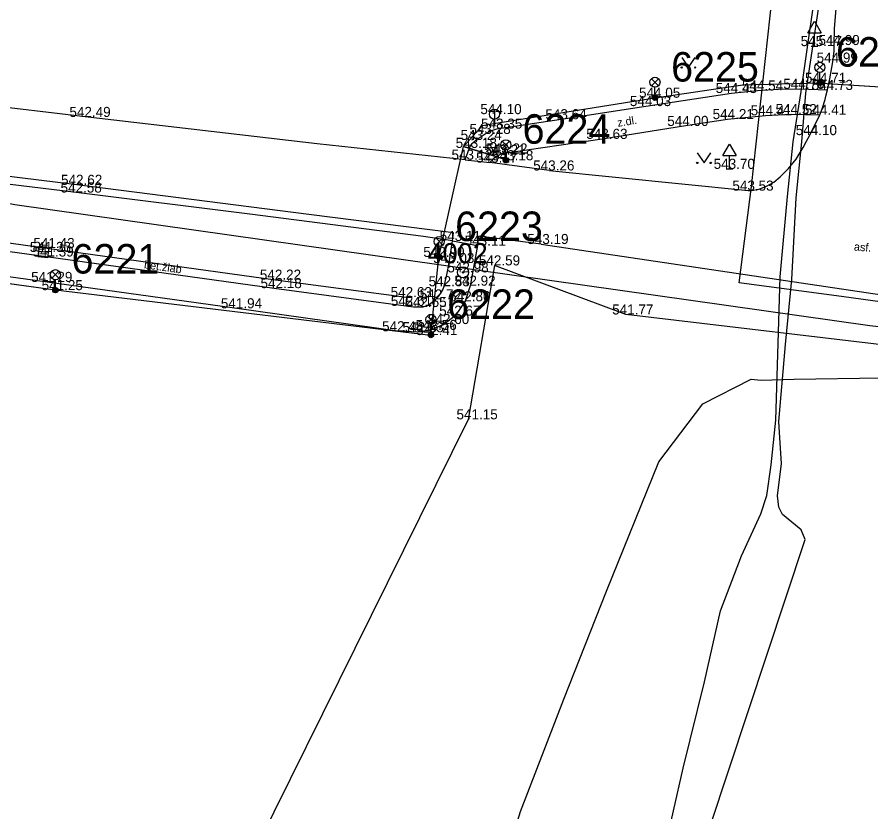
# Model space of a CAD drawing. Extents: x -669393 to -668650, y -1126925 to -1126294.
# Drawn here: x -669358 to -669294.5, y -1126585.2 to -1126526.1 of the extents above; entities that cross this region are included whole.
import ezdxf

# ---------------------------------------------------------------- set-up
doc = ezdxf.new("R2010")
doc.units = 0
for name, color, linetype in [('G_Bod_tecka', 7, 'Continuous'), ('G_Bod_vyska', 7, 'Continuous'), ('G_Bodove_pole', 7, 'Continuous'), ('G_Breh_Teren', 7, 'Continuous'), ('G_Cesty_Schody', 7, 'Continuous'), ('G_Objekty_dopravni', 7, 'Continuous'), ('G_Objekty_technicke', 7, 'Continuous'), ('G_Plochy_zpevnene', 7, 'Continuous'), ('G_Popisy_povrchu', 7, 'Continuous'), ('G_Site-kanalizace', 7, 'Continuous'), ('G_Z_ELsilove_nadz_kotovane', 7, 'Continuous'), ('G_Z_ELsilove_podz_kotovane', 7, 'Continuous'), ('G_Z_SPOJE_podz_geodeticky', 7, 'Continuous'), ('G_Z_SPOJE_podz_kotovane', 7, 'Continuous'), ('G_Z_SPOJE_podz_priblizne', 7, 'Continuous'), ('G_Zelen-okraj', 7, 'Continuous'), ('G_Zelen-Znacky', 7, 'Continuous'), ('Vrstva 1', 7, 'Continuous'), ('Vrstva 4', 7, 'Continuous'), ('Vrstva 62', 7, 'Continuous')]:
    doc.layers.add(name, color=color, linetype=linetype)

msp = doc.modelspace()

# ---------------------------------------------------------------- linework, layer by layer
at = {"layer": 'G_Bod_tecka'}
for p, q in [((-669298.71, -1126528.29), (-669298.71, -1126528.29)), ((-669297.24, -1126528.21), (-669297.24, -1126528.21)), ((-669297.38, -1126529.52), (-669297.38, -1126529.52)), ((-669302.94, -1126531.59), (-669302.94, -1126531.59)), ((-669299.84, -1126531.47), (-669299.84, -1126531.47)), ((-669298.31, -1126531.02), (-669298.31, -1126531.02)), ((-669297.75, -1126531.55), (-669297.75, -1126531.55)), ((-669310.57, -1126532.13), (-669310.57, -1126532.13)), ((-669304.89, -1126531.78), (-669304.89, -1126531.78)), ((-669311.25, -1126532.75), (-669311.25, -1126532.75)), ((-669322.51, -1126533.35), (-669322.51, -1126533.35)), ((-669302.35, -1126533.44), (-669302.35, -1126533.44)), ((-669300.44, -1126533.35), (-669300.44, -1126533.35)), ((-669298.31, -1126533.4), (-669298.31, -1126533.4)), ((-669352.95, -1126533.56), (-669352.95, -1126533.56)), ((-669317.54, -1126533.73), (-669317.54, -1126533.73)), ((-669305.18, -1126533.72), (-669305.18, -1126533.72)), ((-669322.34, -1126534.43), (-669322.34, -1126534.43)), ((-669308.45, -1126534.23), (-669308.45, -1126534.23)), ((-669323.86, -1126535.27), (-669323.86, -1126535.27)), ((-669323.2, -1126534.82), (-669323.2, -1126534.82)), ((-669314.5, -1126535.19), (-669314.5, -1126535.19)), ((-669299.06, -1126534.91), (-669299.06, -1126534.91)), ((-669324.37, -1126535.86), (-669324.37, -1126535.86)), ((-669322.16, -1126536.37), (-669322.16, -1126536.37)), ((-669321.95, -1126536.28), (-669321.95, -1126536.28)), ((-669324.68, -1126536.74), (-669324.68, -1126536.74)), ((-669322.85, -1126536.95), (-669322.85, -1126536.95)), ((-669321.66, -1126536.78), (-669321.66, -1126536.78)), ((-669318.45, -1126537.54), (-669318.45, -1126537.54)), ((-669305.02, -1126537.42), (-669305.02, -1126537.42)), ((-669353.61, -1126539.18), (-669353.61, -1126539.18)), ((-669353.56, -1126538.61), (-669353.56, -1126538.61)), ((-669303.65, -1126539.04), (-669303.65, -1126539.04)), ((-669325.62, -1126542.78), (-669325.62, -1126542.78)), ((-669319.04, -1126543.01), (-669319.04, -1126543.01)), ((-669356.04, -1126543.6), (-669356.04, -1126543.6)), ((-669355.77, -1126543.31), (-669355.77, -1126543.31)), ((-669323.76, -1126543.13), (-669323.76, -1126543.13)), ((-669355.84, -1126543.94), (-669355.84, -1126543.94)), ((-669326.61, -1126543.97), (-669326.61, -1126543.97)), ((-669325.88, -1126544.42), (-669325.88, -1126544.42)), ((-669322.5, -1126544.6), (-669322.5, -1126544.6)), ((-669324.84, -1126545.12), (-669324.84, -1126545.12)), ((-669355.94, -1126545.83), (-669355.94, -1126545.83)), ((-669338.79, -1126545.66), (-669338.79, -1126545.66)), ((-669326.24, -1126546.15), (-669326.24, -1126546.15)), ((-669324.32, -1126546.11), (-669324.32, -1126546.11)), ((-669355.16, -1126546.44), (-669355.16, -1126546.44)), ((-669338.88, -1126546.29), (-669338.88, -1126546.29)), ((-669329.05, -1126546.96), (-669329.05, -1126546.96)), ((-669326.9, -1126547.13), (-669326.9, -1126547.13)), ((-669324.68, -1126547.27), (-669324.68, -1126547.27)), ((-669341.83, -1126547.79), (-669341.83, -1126547.79)), ((-669329.1, -1126547.61), (-669329.1, -1126547.61)), ((-669327.95, -1126547.69), (-669327.95, -1126547.69)), ((-669325.44, -1126548.34), (-669325.44, -1126548.34)), ((-669312.73, -1126548.25), (-669312.73, -1126548.25)), ((-669327.2, -1126549.4), (-669327.2, -1126549.4)), ((-669326.25, -1126548.96), (-669326.25, -1126548.96)), ((-669329.7, -1126549.5), (-669329.7, -1126549.5)), ((-669328.18, -1126549.57), (-669328.18, -1126549.57)), ((-669327.23, -1126549.78), (-669327.23, -1126549.78)), ((-669324.45, -1126556.05), (-669324.45, -1126556.05))]:
    msp.add_line(p, q, dxfattribs=at)
at = {"layer": 'G_Bodove_pole'}
for radius in [0.412, 0.05]:
    msp.add_circle((-669324.84, -1126545.12), radius, dxfattribs=at)
at = {"layer": 'G_Breh_Teren'}
for points in [[(-669325.62, -1126542.78), (-669327.79, -1126542.44), (-669340.7, -1126540.78), (-669353.61, -1126539.18), (-669369.57, -1126537.24), (-669385.54, -1126535.32), (-669388.78, -1126534.926)], [(-669325.62, -1126542.78), (-669327.79, -1126542.44), (-669340.7, -1126540.78), (-669353.61, -1126539.18), (-669369.57, -1126537.24), (-669385.54, -1126535.32), (-669388.78, -1126534.926)], [(-669253.52, -1126555.73), (-669254.03, -1126555.64), (-669254.54, -1126555.56), (-669256.55, -1126555.24), (-669258.55, -1126554.92), (-669262.47, -1126554.31), (-669266.4, -1126553.72), (-669269.9, -1126553.23), (-669273.41, -1126552.75), (-669278.15, -1126552.15), (-669282.9, -1126551.62), (-669286.72, -1126551.24), (-669290.54, -1126550.87), (-669312.73, -1126548.25), (-669322.5, -1126544.6)]]:
    msp.add_lwpolyline(points, dxfattribs=at)
at = {"layer": 'G_Cesty_Schody'}
msp.add_lwpolyline([(-669385.563, -1126539.824), (-669383.61, -1126540.11), (-669368.3, -1126542.23), (-669355.84, -1126543.94), (-669338.88, -1126546.29), (-669329.1, -1126547.61)], dxfattribs=at)
msp.add_lwpolyline([(-669385.563, -1126539.824), (-669383.61, -1126540.11), (-669368.3, -1126542.23), (-669355.84, -1126543.94), (-669338.88, -1126546.29), (-669329.1, -1126547.61)], dxfattribs=at)
at = {"layer": 'G_Objekty_dopravni'}
for p, q in [((-669299.21, -1126527.29), (-669298.71, -1126526.44)), ((-669298.71, -1126526.44), (-669298.21, -1126527.29)), ((-669299.21, -1126527.29), (-669298.21, -1126527.29)), ((-669298.71, -1126528.29), (-669298.71, -1126527.29)), ((-669298.96, -1126528.29), (-669298.46, -1126528.29)), ((-669305.52, -1126536.42), (-669305.02, -1126535.57)), ((-669305.02, -1126535.57), (-669304.52, -1126536.42)), ((-669305.52, -1126536.42), (-669304.52, -1126536.42)), ((-669305.02, -1126537.42), (-669305.02, -1126536.42)), ((-669305.27, -1126537.42), (-669304.77, -1126537.42))]:
    msp.add_line(p, q, dxfattribs=at)
at = {"layer": 'G_Objekty_technicke'}
for p, q in [((-669298.575, -1126529.605), (-669298.045, -1126530.135)), ((-669298.575, -1126530.135), (-669298.045, -1126529.605)), ((-669298.31, -1126531.02), (-669298.31, -1126530.245)), ((-669310.835, -1126530.715), (-669310.305, -1126531.245)), ((-669310.835, -1126531.245), (-669310.305, -1126530.715)), ((-669310.57, -1126532.13), (-669310.57, -1126531.355)), ((-669321.925, -1126535.365), (-669321.395, -1126535.895)), ((-669321.925, -1126535.895), (-669321.395, -1126535.365)), ((-669321.66, -1126536.78), (-669321.66, -1126536.005)), ((-669326.875, -1126542.555), (-669326.345, -1126543.085)), ((-669326.875, -1126543.085), (-669326.345, -1126542.555)), ((-669326.61, -1126543.97), (-669326.61, -1126543.195)), ((-669355.425, -1126545.025), (-669354.895, -1126545.555)), ((-669355.425, -1126545.555), (-669354.895, -1126545.025)), ((-669355.16, -1126546.44), (-669355.16, -1126545.665)), ((-669327.495, -1126548.365), (-669326.965, -1126548.895)), ((-669327.495, -1126548.895), (-669326.965, -1126548.365)), ((-669327.23, -1126549.78), (-669327.23, -1126549.005))]:
    msp.add_line(p, q, dxfattribs=at)
for centre, radius in [((-669298.31, -1126529.87), 0.375), ((-669310.57, -1126530.98), 0.375), ((-669298.31, -1126531.02), 0.2), ((-669298.31, -1126531.02), 0.18), ((-669298.31, -1126531.02), 0.16), ((-669298.31, -1126531.02), 0.14), ((-669298.31, -1126531.02), 0.12), ((-669298.31, -1126531.02), 0.1), ((-669298.31, -1126531.02), 0.08), ((-669298.31, -1126531.02), 0.06), ((-669298.31, -1126531.02), 0.04), ((-669298.31, -1126531.02), 0.02), ((-669310.57, -1126532.13), 0.2), ((-669310.57, -1126532.13), 0.18), ((-669310.57, -1126532.13), 0.16), ((-669310.57, -1126532.13), 0.14), ((-669310.57, -1126532.13), 0.12), ((-669310.57, -1126532.13), 0.1), ((-669310.57, -1126532.13), 0.08), ((-669310.57, -1126532.13), 0.06), ((-669310.57, -1126532.13), 0.04), ((-669310.57, -1126532.13), 0.02), ((-669321.66, -1126535.63), 0.375), ((-669321.66, -1126536.78), 0.2), ((-669321.66, -1126536.78), 0.18), ((-669321.66, -1126536.78), 0.16), ((-669321.66, -1126536.78), 0.14), ((-669321.66, -1126536.78), 0.12), ((-669321.66, -1126536.78), 0.1), ((-669321.66, -1126536.78), 0.08), ((-669321.66, -1126536.78), 0.06), ((-669321.66, -1126536.78), 0.04), ((-669321.66, -1126536.78), 0.02), ((-669326.61, -1126542.82), 0.375), ((-669326.61, -1126543.97), 0.2), ((-669326.61, -1126543.97), 0.18), ((-669326.61, -1126543.97), 0.16), ((-669326.61, -1126543.97), 0.14), ((-669326.61, -1126543.97), 0.12), ((-669326.61, -1126543.97), 0.1), ((-669326.61, -1126543.97), 0.08), ((-669326.61, -1126543.97), 0.06), ((-669326.61, -1126543.97), 0.04), ((-669326.61, -1126543.97), 0.02), ((-669355.16, -1126545.29), 0.375), ((-669355.16, -1126546.44), 0.2), ((-669355.16, -1126546.44), 0.18), ((-669355.16, -1126546.44), 0.16), ((-669355.16, -1126546.44), 0.14), ((-669355.16, -1126546.44), 0.12), ((-669355.16, -1126546.44), 0.1), ((-669355.16, -1126546.44), 0.08), ((-669355.16, -1126546.44), 0.06), ((-669355.16, -1126546.44), 0.04), ((-669355.16, -1126546.44), 0.02), ((-669327.23, -1126548.63), 0.375), ((-669327.23, -1126549.78), 0.2), ((-669327.23, -1126549.78), 0.18), ((-669327.23, -1126549.78), 0.16), ((-669327.23, -1126549.78), 0.14), ((-669327.23, -1126549.78), 0.12), ((-669327.23, -1126549.78), 0.1), ((-669327.23, -1126549.78), 0.08), ((-669327.23, -1126549.78), 0.06), ((-669327.23, -1126549.78), 0.04), ((-669327.23, -1126549.78), 0.02)]:
    msp.add_circle(centre, radius, dxfattribs=at)
at = {"layer": 'G_Plochy_zpevnene'}
for p, q in [((-669324.68, -1126536.74), (-669322.85, -1126536.95)), ((-669318.45, -1126537.54), (-669322.85, -1126536.95)), ((-669318.45, -1126537.54), (-669303.65, -1126539.04)), ((-669325.62, -1126542.78), (-669325.55, -1126542.18)), ((-669325.62, -1126542.78), (-669323.76, -1126543.13)), ((-669323.76, -1126543.13), (-669323.66, -1126542.42)), ((-669319.04, -1126543.01), (-669289.35, -1126547.43)), ((-669329.05, -1126546.96), (-669329.1, -1126547.61))]:
    msp.add_line(p, q, dxfattribs=at)
for points in [[(-669297.23, -1126526.98), (-669296.85, -1126522.54), (-669295.36, -1126509.24), (-669294.28, -1126498.88), (-669293.24, -1126488.52), (-669292.4, -1126479.65), (-669291.57, -1126470.78)], [(-669297.75, -1126531.55), (-669297.57, -1126530.72), (-669297.41, -1126529.89), (-669297.34, -1126529.47), (-669297.31, -1126529.26), (-669297.29, -1126529.05), (-669297.25, -1126528.63), (-669297.24, -1126528.21), (-669297.23, -1126526.98)], [(-669324.68, -1126536.74), (-669335.7, -1126535.55), (-669352.95, -1126533.56), (-669360.92, -1126532.6), (-669372.86, -1126531.08), (-669384.79, -1126529.51), (-669389.5, -1126528.86), (-669393.127, -1126528.31)], [(-669324.68, -1126536.74), (-669335.7, -1126535.55), (-669352.95, -1126533.56), (-669360.92, -1126532.6), (-669372.86, -1126531.08), (-669384.79, -1126529.51), (-669389.5, -1126528.86), (-669393.127, -1126528.31)], [(-669324.68, -1126536.74), (-669324.37, -1126535.86), (-669324.16, -1126535.54), (-669323.86, -1126535.27), (-669323.2, -1126534.82), (-669322.78, -1126534.58), (-669322.34, -1126534.43), (-669317.54, -1126533.73), (-669311.25, -1126532.75), (-669304.89, -1126531.78), (-669302.94, -1126531.59), (-669301.39, -1126531.49), (-669299.84, -1126531.47), (-669297.75, -1126531.55)], [(-669298.31, -1126533.4), (-669298.13, -1126532.95), (-669298.05, -1126532.72), (-669297.98, -1126532.49), (-669297.92, -1126532.26), (-669297.86, -1126532.02), (-669297.75, -1126531.55)], [(-669322.85, -1126536.95), (-669322.52, -1126536.6), (-669322.16, -1126536.37), (-669321.95, -1126536.28), (-669314.5, -1126535.19), (-669308.45, -1126534.23), (-669305.18, -1126533.72), (-669302.35, -1126533.44), (-669300.44, -1126533.35), (-669298.31, -1126533.4)], [(-669300.07, -1126536.71), (-669299.55, -1126535.82), (-669299.3, -1126535.37), (-669299.06, -1126534.91), (-669298.31, -1126533.4)], [(-669325.55, -1126542.18), (-669336.3, -1126540.81), (-669353.56, -1126538.61), (-669369.53, -1126536.66), (-669385.5, -1126534.77), (-669389.177, -1126534.322)], [(-669325.55, -1126542.18), (-669336.3, -1126540.81), (-669353.56, -1126538.61), (-669369.53, -1126536.66), (-669385.5, -1126534.77), (-669389.177, -1126534.322)], [(-669303.65, -1126539.04), (-669303.52, -1126539.03), (-669303.39, -1126539.03), (-669302.83, -1126538.92), (-669302.28, -1126538.71), (-669301.74, -1126538.4), (-669301.26, -1126538.02), (-669300.63, -1126537.39), (-669300.07, -1126536.71)], [(-669386.03, -1126539.112), (-669383.6, -1126539.47), (-669368.29, -1126541.58), (-669355.77, -1126543.31), (-669338.79, -1126545.66), (-669329.05, -1126546.96)], [(-669386.03, -1126539.112), (-669383.6, -1126539.47), (-669368.29, -1126541.58), (-669355.77, -1126543.31), (-669338.79, -1126545.66), (-669329.05, -1126546.96)], [(-669323.76, -1126543.13), (-669324.32, -1126546.11), (-669324.68, -1126547.27), (-669325.44, -1126548.34), (-669326.25, -1126548.96), (-669327.2, -1126549.4), (-669328.18, -1126549.57), (-669329.7, -1126549.5), (-669341.83, -1126547.79), (-669355.94, -1126545.83), (-669367.68, -1126544.2), (-669382.66, -1126542.15), (-669384.18, -1126541.929)], [(-669323.76, -1126543.13), (-669324.32, -1126546.11), (-669324.68, -1126547.27), (-669325.44, -1126548.34), (-669326.25, -1126548.96), (-669327.2, -1126549.4), (-669328.18, -1126549.57), (-669329.7, -1126549.5), (-669341.83, -1126547.79), (-669355.94, -1126545.83), (-669367.68, -1126544.2), (-669382.66, -1126542.15), (-669384.18, -1126541.929)], [(-669329.1, -1126547.61), (-669328.53, -1126547.67), (-669327.95, -1126547.69), (-669327.8, -1126547.68), (-669327.66, -1126547.64), (-669327.4, -1126547.52), (-669327.14, -1126547.34), (-669326.9, -1126547.13), (-669326.68, -1126546.91), (-669326.49, -1126546.67), (-669326.34, -1126546.42), (-669326.24, -1126546.15), (-669326.04, -1126545.29), (-669325.88, -1126544.42), (-669325.62, -1126542.78)], [(-669319.04, -1126543.01), (-669323.66, -1126542.42)]]:
    msp.add_lwpolyline(points, dxfattribs=at)
at = {"layer": 'G_Site-kanalizace'}
for p, q in [((-669322.51, -1126532.975), (-669322.51, -1126534.225)), ((-669355.668, -1126543.643), (-669356.412, -1126543.557))]:
    msp.add_line(p, q, dxfattribs=at)
msp.add_lwpolyline([(-669355.624, -1126543.272), (-669356.369, -1126543.185), (-669356.456, -1126543.93), (-669355.711, -1126544.017)], close=True, dxfattribs=at)
msp.add_circle((-669322.51, -1126533.35), 0.375, dxfattribs=at)
at = {"layer": 'G_Z_ELsilove_nadz_kotovane'}
msp.add_lwpolyline([(-669313.545, -1126607.689), (-669299.411, -1126564.986)], dxfattribs=at)
at = {"layer": 'G_Z_ELsilove_podz_kotovane'}
for points in [[(-669301.875, -1126558.955), (-669301.588, -1126556.109), (-669301.4, -1126550.39), (-669301.272, -1126545.461), (-669300.712, -1126539.465), (-669300.29, -1126535.404), (-669299.688, -1126531.676), (-669298.314, -1126521.946), (-669297.269, -1126515.174), (-669296.892, -1126508.835), (-669296.268, -1126502.722), (-669295.593, -1126496.807), (-669295.195, -1126491.27), (-669294.703, -1126484.965), (-669294.159, -1126479.826)], [(-669301.287, -1126557.416), (-669301.361, -1126556.208), (-669300.863, -1126550.473), (-669300.382, -1126545.645), (-669300.074, -1126539.564), (-669299.661, -1126535.407), (-669299.361, -1126531.789), (-669297.88, -1126522.048), (-669296.989, -1126515.295), (-669296.655, -1126508.855), (-669295.996, -1126502.742), (-669295.286, -1126496.876), (-669294.857, -1126491.104), (-669294.238, -1126484.98)], [(-669324.8, -1126535.75), (-669323.4, -1126534.19), (-669322.56, -1126534.05), (-669310.57, -1126532.13), (-669304.03, -1126531.16), (-669298.31, -1126531.02), (-669298.17, -1126531.04), (-669289.42, -1126531.6)], [(-669383.801, -1126542.505), (-669383.09, -1126542.61), (-669355.16, -1126546.41), (-669327.23, -1126549.78), (-669326.64, -1126543.99), (-669324.8, -1126535.75)], [(-669324.8, -1126535.75), (-669321.62, -1126536.75)], [(-669299.411, -1126564.986), (-669299.7, -1126564.265), (-669301.08, -1126563.12), (-669301.369, -1126562.571), (-669301.454, -1126561.737), (-669301.171, -1126559.329), (-669301.287, -1126557.416)], [(-669313.948, -1126607.229), (-669314.541, -1126606.53), (-669314.93, -1126605.918), (-669314.79, -1126605.28), (-669311.156, -1126594.293), (-669309.913, -1126588.335), (-669308.475, -1126581.99), (-669306.879, -1126575.581), (-669305.691, -1126570.294), (-669304.129, -1126566.2), (-669302.694, -1126563.085), (-669302.26, -1126561.706), (-669301.924, -1126559.44), (-669301.875, -1126558.955)]]:
    msp.add_lwpolyline(points, dxfattribs=at)
at = {"layer": 'G_Z_SPOJE_podz_geodeticky'}
for points in [[(-669296.52, -1126546.94), (-669304.3, -1126545.89), (-669303.4, -1126538.72), (-669300.8, -1126514.91), (-669302.66, -1126500.89), (-669301.93, -1126471.1)], [(-669244.58, -1126554.62), (-669294.58, -1126549.1), (-669358.17, -1126540.1), (-669385.82, -1126534.54)], [(-669289.15, -1126547.95), (-669296.52, -1126546.94)], [(-669330.33, -1126623.905), (-669330.16, -1126623.29), (-669323.72, -1126595.49), (-669320.58, -1126585.22), (-669317.35, -1126576.85), (-669314.18, -1126568.82), (-669310.28, -1126559.22), (-669307, -1126554.89), (-669303.42, -1126553.07), (-669302.68, -1126553.14), (-669300.22, -1126553.06), (-669293.76, -1126552.97)]]:
    msp.add_lwpolyline(points, dxfattribs=at)
at = {"layer": 'G_Z_SPOJE_podz_kotovane'}
for points in [[(-669296.52, -1126546.94), (-669304.3, -1126545.89), (-669303.4, -1126538.72), (-669300.8, -1126514.91), (-669302.66, -1126500.89), (-669301.93, -1126471.1)], [(-669289.15, -1126547.95), (-669296.52, -1126546.94)]]:
    msp.add_lwpolyline(points, dxfattribs=at)
at = {"layer": 'G_Z_SPOJE_podz_priblizne'}
for points in [[(-669296.52, -1126546.94), (-669304.3, -1126545.89), (-669303.4, -1126538.72), (-669300.8, -1126514.91), (-669302.66, -1126500.89), (-669301.93, -1126471.1)], [(-669244.58, -1126554.62), (-669294.58, -1126549.1), (-669358.17, -1126540.1), (-669385.82, -1126534.54)], [(-669289.15, -1126547.95), (-669296.52, -1126546.94)]]:
    msp.add_lwpolyline(points, dxfattribs=at)
at = {"layer": 'G_Zelen-okraj'}
msp.add_lwpolyline([(-669322.5, -1126544.6), (-669324.45, -1126556.05), (-669346.131, -1126599.851)], dxfattribs=at)
at = {"layer": 'G_Zelen-Znacky'}
for p, q in [((-669308.58, -1126529.13), (-669308.08, -1126529.88)), ((-669308.08, -1126529.88), (-669307.58, -1126529.13)), ((-669307.42, -1126536.23), (-669306.92, -1126536.98)), ((-669306.92, -1126536.98), (-669306.42, -1126536.23))]:
    msp.add_line(p, q, dxfattribs=at)
for centre in [(-669308.58, -1126529.88), (-669307.58, -1126529.88), (-669307.42, -1126536.98), (-669306.42, -1126536.98)]:
    msp.add_circle(centre, 0.05, dxfattribs=at)
at = {"layer": 'Vrstva 1'}
for p, q in [((-669298.31, -1126531.017), (-669298.31, -1126531.017)), ((-669310.573, -1126532.127), (-669310.573, -1126532.127)), ((-669321.619, -1126536.75), (-669321.619, -1126536.75)), ((-669326.636, -1126543.988), (-669326.636, -1126543.988)), ((-669355.159, -1126546.406), (-669355.159, -1126546.406)), ((-669327.23, -1126549.78), (-669327.23, -1126549.78))]:
    msp.add_line(p, q, dxfattribs=at)
at = {"layer": 'Vrstva 62'}
for p, q in [((-669310.573, -1126532.127), (-669304.032, -1126531.164)), ((-669304.032, -1126531.164), (-669298.31, -1126531.017)), ((-669298.31, -1126531.017), (-669298.171, -1126531.037)), ((-669298.171, -1126531.037), (-669289.415, -1126531.597)), ((-669322.558, -1126534.053), (-669310.573, -1126532.127)), ((-669323.403, -1126534.189), (-669322.558, -1126534.053)), ((-669324.797, -1126535.745), (-669323.403, -1126534.189)), ((-669326.636, -1126543.988), (-669324.797, -1126535.745)), ((-669324.797, -1126535.745), (-669321.619, -1126536.75)), ((-669321.619, -1126536.75), (-669324.797, -1126535.745)), ((-669383.09, -1126542.606), (-669355.159, -1126546.406)), ((-669327.23, -1126549.78), (-669326.636, -1126543.988)), ((-669355.159, -1126546.406), (-669327.23, -1126549.78))]:
    msp.add_line(p, q, dxfattribs=at)

# ---------------------------------------------------------------- texts
at = {"layer": 'G_Bod_vyska'}
for s, p in [('545.17', (-669299.732, -1126528.29)), ('544.99', (-669298.408, -1126528.21)), ('544.99', (-669298.548, -1126529.52)), ('544.71', (-669299.412, -1126531.02)), ('544.54', (-669304.104, -1126531.59)), ('544.70', (-669301.026, -1126531.47)), ('544.73', (-669298.914, -1126531.55)), ('544.05', (-669311.756, -1126532.13)), ('544.43', (-669306.054, -1126531.78)), ('544.03', (-669312.436, -1126532.75)), ('542.49', (-669354.116, -1126533.56)), ('544.10', (-669323.554, -1126533.35)), ('544.41', (-669303.452, -1126533.44)), ('544.52', (-669301.604, -1126533.35)), ('544.41', (-669299.412, -1126533.4)), ('543.64', (-669318.718, -1126533.73)), ('544.00', (-669309.657, -1126534.23)), ('544.21', (-669306.282, -1126533.72)), ('543.28', (-669324.364, -1126534.82)), ('543.35', (-669323.504, -1126534.43)), ('544.10', (-669300.104, -1126534.91)), ('543.24', (-669325.024, -1126535.27)), ('543.63', (-669315.678, -1126535.19)), ('543.18', (-669325.392, -1126535.86)), ('543.12', (-669325.702, -1126536.74)), ('543.21', (-669323.262, -1126536.37)), ('543.22', (-669323.114, -1126536.28)), ('543.18', (-669322.682, -1126536.78)), ('543.17', (-669323.872, -1126536.95)), ('543.70', (-669306.206, -1126537.42)), ('543.26', (-669319.628, -1126537.54)), ('542.62', (-669354.738, -1126538.61)), ('542.58', (-669354.774, -1126539.18)), ('543.53', (-669304.814, -1126539.04)), ('543.11', (-669326.581, -1126542.78)), ('543.11', (-669324.721, -1126543.13)), ('543.19', (-669320.064, -1126543.01)), ('541.33', (-669357.062, -1126543.6)), ('541.43', (-669356.792, -1126543.31)), ('541.39', (-669356.864, -1126543.94)), ('542.90', (-669327.798, -1126543.97)), ('543.03', (-669327.066, -1126544.42)), ('542.59', (-669323.666, -1126544.6)), ('542.22', (-669339.954, -1126545.66)), ('542.98', (-669326.006, -1126545.12)), ('541.29', (-669356.964, -1126545.83)), ('542.18', (-669339.902, -1126546.29)), ('542.83', (-669327.404, -1126546.15)), ('542.92', (-669325.486, -1126546.11)), ('541.25', (-669356.182, -1126546.44)), ('542.63', (-669330.228, -1126546.96)), ('542.61', (-669330.216, -1126547.61)), ('542.72', (-669328.064, -1126547.13)), ('542.80', (-669325.866, -1126547.27)), ('541.94', (-669342.854, -1126547.79)), ('542.65', (-669329.128, -1126547.69)), ('542.67', (-669326.618, -1126548.34)), ('541.77', (-669313.752, -1126548.25)), ('542.48', (-669330.864, -1126549.5)), ('542.56', (-669328.378, -1126549.4)), ('542.60', (-669327.449, -1126548.96)), ('542.53', (-669329.344, -1126549.57)), ('542.41', (-669328.332, -1126549.78)), ('541.15', (-669325.331, -1126556.05))]:
    msp.add_text(s, height=0.75, dxfattribs=at).set_placement(p)
at = {"layer": 'G_Bodove_pole'}
msp.add_text('4002', height=1.5, dxfattribs=at).set_placement((-669327.473, -1126544.44))
at = {"layer": 'G_Popisy_povrchu'}
for s, rotation, p in [('z.dl.', 9.02582, (-669313.326, -1126534.293)), ('asf.', 355.35309, (-669295.789, -1126543.486)), ('bet.žlab', 352.06492, (-669348.591, -1126544.808))]:
    msp.add_text(s, height=0.6, rotation=rotation, dxfattribs=at).set_placement(p)
at = {"layer": 'Vrstva 4'}
for s, p in [('6226', (-669297.107, -1126529.815)), ('6225', (-669309.37, -1126530.926)), ('6224', (-669320.416, -1126535.548)), ('6223', (-669325.433, -1126542.786)), ('6221', (-669353.956, -1126545.204)), ('6222', (-669326.026, -1126548.578))]:
    msp.add_text(s, height=2.1939, dxfattribs=at).set_placement(p)

doc.saveas('drawing.dxf')
